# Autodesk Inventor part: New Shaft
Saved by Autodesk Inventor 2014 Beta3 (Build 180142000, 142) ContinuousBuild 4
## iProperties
Created: 2011-01
Part Number: New Shaft
Material: Steel
Document SubType Name: Modeling
Designer: Beta-8540w
Density: 1 g/cm^3
Appearance: Steel
CustomPartVersion: 1
Author: Beta-8540w
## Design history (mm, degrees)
sketch "Main Sketch"
  geometry: L1 (0, 0)-(51, 0) reference; L2 (0, 0)-(0, 5); L3 (0, 5)-(10, 5); L4 (10, 5)-(10, 6); L5 (10, 6)-(13, 6); L6 (13, 6)-(13, 12.5); L7 (25, 12.5)-(25, 6); L8 (13, 12.5)-(25, 12.5); L9 (41, 6)-(41, 5); L10 (25, 6)-(41, 6); L11 (51, 5)-(51, 0); L12 (41, 5)-(51, 5)
  constraints: 24 end point, 7 horizontal, 6 vertical
  dimensions: "d3" = 10 diameter of L3 L1 (derived); "d4" = 12 diameter of L5 L1 (derived); "d5" = 25 diameter of L8 L1 (derived); "d6" = 12 diameter of L10 L1 (derived); "d7" = 10 diameter of L12 L1 (derived)
revolve "Revolution1" sketch "Main Sketch" stored, may be unused: angle "d8" = 0 deg
chamfer "Chamfer1" distance "d9" = 0.3; stored, may be unused: second distance "d10" = 0.125, angle "d11" = 45 deg
chamfer "Chamfer2" distance "d12" = 0.3; stored, may be unused: second distance "d13" = 0.125, angle "d14" = 45 deg
node "Spur Gear Teeth2"
body "Solid1"
feature "Spur Gear Feature 1"
other parameters: "d0" = 0, "d1" = 0, "d2" = 0
